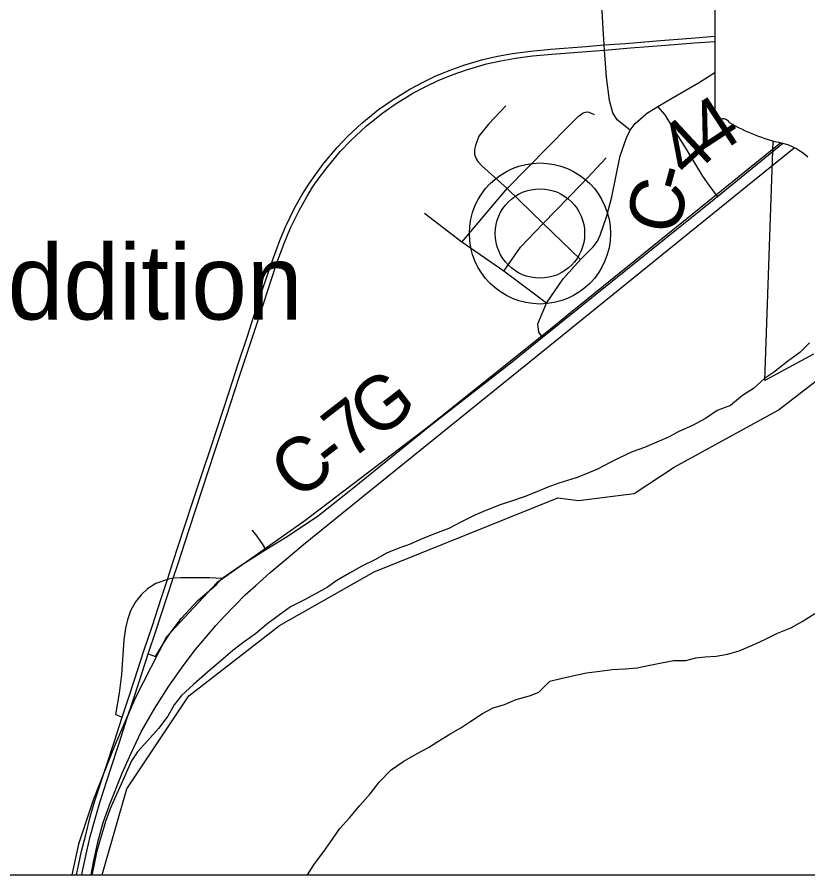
# Model space of a CAD drawing. Extents: x 0 to 34, y 0 to 22.
# Drawn here: x 6.612 to 7.446, y 14.1 to 15.005 of the extents above; entities that cross this region are included whole.
import ezdxf

# ---------------------------------------------------------------- set-up
doc = ezdxf.new("R2010")
doc.units = 0
for name, color, linetype in [('Default', 7, 'Continuous'), ('GM_X_County_Road', 7, 'Continuous'), ('GM_X_County_Road_Text', 7, 'Continuous'), ('GM_X_Interchange_Ramps', 7, 'Continuous'), ('GM_X_Major_River', 7, 'Continuous'), ('GM_X_Rail_Line', 7, 'Continuous'), ('GM_X_Section', 7, 'Continuous'), ('GM_X_State_Route', 7, 'Continuous'), ('GM_X_State_Shield', 7, 'Continuous'), ('GM_X_Township_Road', 7, 'Continuous'), ('GM_X_Unincorporated', 7, 'Continuous'), ('GM_X_Unincorporated_Location', 7, 'Continuous'), ('GM_X_Unincorporated_Text', 7, 'Continuous'), ('SH_Cut_Line', 7, 'Continuous'), ('SH_Data', 7, 'Continuous')]:
    doc.layers.add(name, color=color, linetype=linetype)

msp = doc.modelspace()

# ---------------------------------------------------------------- linework, layer by layer
at = {"layer": 'Default'}
for p, q in [((7.41471, 14.59015), (7.49082, 14.64909)), ((7.30502, 14.53008), (7.41471, 14.59015)), ((7.26298, 14.50243), (7.30502, 14.53008)), ((7.20414, 14.49508), (7.26298, 14.50243)), ((6.98847, 14.41957), (7.18239, 14.49774)), ((7.18239, 14.49774), (7.20414, 14.49508)), ((6.88889, 14.36327), (6.98847, 14.41957)), ((6.79317, 14.28882), (6.88889, 14.36327)), ((6.72773, 14.19078), (6.79317, 14.28882)), ((6.70166, 14.1), (6.72773, 14.19078)), ((2.1, 14.1), (6.70166, 14.1))]:
    msp.add_line(p, q, dxfattribs=at)
at = {"layer": 'GM_X_County_Road'}
for p, q in [((7.33067, 14.93583), (7.34804, 14.94647)), ((7.30175, 14.91894), (7.33067, 14.93583)), ((7.28799, 14.91083), (7.30175, 14.91894)), ((7.27602, 14.90331), (7.28799, 14.91083)), ((7.26391, 14.89277), (7.27522, 14.9028)), ((7.27522, 14.9028), (7.27602, 14.90331)), ((7.2588, 14.88565), (7.26391, 14.89277)), ((7.25497, 14.8778), (7.2588, 14.88565)), ((7.24804, 14.85864), (7.25497, 14.8778)), ((7.38738, 14.84583), (7.41968, 14.87194)), ((7.23926, 14.81549), (7.24804, 14.85864)), ((7.35075, 14.81566), (7.38738, 14.84583)), ((7.16638, 14.66727), (7.35075, 14.81566)), ((7.23399, 14.79526), (7.23926, 14.81549)), ((7.22693, 14.77491), (7.23399, 14.79526)), ((7.22416, 14.76879), (7.22693, 14.77491)), ((7.20645, 14.74914), (7.21973, 14.76272)), ((7.21973, 14.76272), (7.22416, 14.76879)), ((7.18784, 14.72871), (7.20645, 14.74914)), ((7.17033, 14.70324), (7.18784, 14.72871)), ((7.16121, 14.68126), (7.17033, 14.70324)), ((7.1623, 14.67251), (7.16121, 14.68126)), ((7.16638, 14.66727), (7.1623, 14.67251)), ((7.13461, 14.64157), (7.16638, 14.66727)), ((7.04873, 14.57481), (7.13461, 14.64157)), ((7.00271, 14.53742), (7.04873, 14.57481)), ((6.96588, 14.50753), (7.00271, 14.53742)), ((6.93001, 14.47931), (6.96588, 14.50753)), ((6.89679, 14.45693), (6.93001, 14.47931)), ((6.87441, 14.44317), (6.89679, 14.45693)), ((6.84717, 14.42621), (6.87441, 14.44317)), ((6.82785, 14.41273), (6.84717, 14.42621))]:
    msp.add_line(p, q, dxfattribs=at)
at = {"layer": 'GM_X_Interchange_Ramps'}
for p, q in [((6.77044, 14.41177), (6.75819, 14.40731)), ((6.77666, 14.41304), (6.77044, 14.41177)), ((6.78451, 14.41339), (6.77666, 14.41304)), ((6.81536, 14.41351), (6.78451, 14.41339)), ((6.82785, 14.41273), (6.81536, 14.41351)), ((6.82192, 14.40585), (6.82785, 14.41273)), ((6.7495, 14.40168), (6.74276, 14.39556)), ((6.75819, 14.40731), (6.7495, 14.40168)), ((6.80267, 14.38937), (6.82192, 14.40585)), ((6.74276, 14.39556), (6.73685, 14.38791)), ((6.73685, 14.38791), (6.73164, 14.37846)), ((6.78536, 14.37089), (6.80267, 14.38937)), ((6.73164, 14.37846), (6.72823, 14.36894)), ((6.72823, 14.36894), (6.72607, 14.36032)), ((6.77334, 14.35504), (6.78536, 14.37089)), ((6.72607, 14.36032), (6.72462, 14.34802)), ((6.76597, 14.34378), (6.77334, 14.35504)), ((6.72462, 14.34802), (6.72204, 14.31153)), ((6.75805, 14.33023), (6.76597, 14.34378)), ((6.75028, 14.33325), (6.75805, 14.33023)), ((6.72204, 14.31153), (6.71954, 14.29179)), ((6.71954, 14.29179), (6.71553, 14.26914)), ((6.71553, 14.26914), (6.7227, 14.26639))]:
    msp.add_line(p, q, dxfattribs=at)
at = {"layer": 'GM_X_Major_River'}
for p, q in [((7.44804, 14.66133), (7.43763, 14.65127)), ((7.43763, 14.65127), (7.42455, 14.64154)), ((7.42455, 14.64154), (7.41, 14.62989)), ((7.41, 14.62989), (7.40027, 14.62363)), ((7.40027, 14.62363), (7.38872, 14.61317)), ((7.38872, 14.61317), (7.37712, 14.60574)), ((7.37712, 14.60574), (7.36444, 14.59526)), ((7.35052, 14.59007), (7.33818, 14.58148)), ((7.36444, 14.59526), (7.35052, 14.59007)), ((7.33818, 14.58148), (7.3243, 14.57401)), ((7.3243, 14.57401), (7.31002, 14.56767)), ((7.2999, 14.56217), (7.28674, 14.55661)), ((7.31002, 14.56767), (7.2999, 14.56217)), ((7.28674, 14.55661), (7.27397, 14.55106)), ((7.2608, 14.54626), (7.24728, 14.53993)), ((7.27397, 14.55106), (7.2608, 14.54626)), ((7.23752, 14.53519), (7.22439, 14.52811)), ((7.24728, 14.53993), (7.23752, 14.53519)), ((7.22439, 14.52811), (7.21161, 14.52294)), ((7.20183, 14.51896), (7.18344, 14.51321)), ((7.21161, 14.52294), (7.20183, 14.51896)), ((7.17178, 14.50922), (7.16014, 14.50408)), ((7.18344, 14.51321), (7.17178, 14.50922)), ((7.14698, 14.49892), (7.13344, 14.49414)), ((7.16014, 14.50408), (7.14698, 14.49892)), ((7.12139, 14.49051), (7.10824, 14.48498)), ((7.13344, 14.49414), (7.12139, 14.49051)), ((7.10824, 14.48498), (7.09472, 14.47943)), ((7.08009, 14.47197), (7.06733, 14.4653)), ((7.09472, 14.47943), (7.08009, 14.47197)), ((7.06733, 14.4653), (7.05342, 14.46013)), ((7.03989, 14.45496), (7.02674, 14.44905)), ((7.05342, 14.46013), (7.03989, 14.45496)), ((7.01471, 14.44466), (7.00155, 14.43951)), ((7.02674, 14.44905), (7.01471, 14.44466)), ((7.00155, 14.43951), (6.98994, 14.43286)), ((6.97568, 14.42578), (6.96256, 14.41835)), ((6.98994, 14.43286), (6.97568, 14.42578)), ((6.96256, 14.41835), (6.94907, 14.41053)), ((6.94907, 14.41053), (6.93936, 14.40353)), ((6.93936, 14.40353), (6.92661, 14.39649)), ((6.91424, 14.38982), (6.90036, 14.38275)), ((6.92661, 14.39649), (6.91424, 14.38982)), ((6.90036, 14.38275), (6.88727, 14.37343)), ((6.88727, 14.37343), (6.87494, 14.36411)), ((7.44009, 14.36721), (7.45356, 14.37581)), ((6.87494, 14.36411), (6.86338, 14.35443)), ((7.42809, 14.36053), (7.44009, 14.36721)), ((6.86338, 14.35443), (6.85142, 14.34588)), ((7.40142, 14.34864), (7.41418, 14.35496)), ((7.41418, 14.35496), (7.42809, 14.36053)), ((6.85142, 14.34588), (6.83947, 14.33657)), ((7.3879, 14.34232), (7.40142, 14.34864)), ((6.83947, 14.33657), (6.82642, 14.32534)), ((7.36156, 14.33271), (7.37361, 14.33636)), ((7.37361, 14.33636), (7.3879, 14.34232)), ((7.29163, 14.3238), (7.30484, 14.32633)), ((7.30484, 14.32633), (7.31735, 14.32619)), ((7.31735, 14.32619), (7.3279, 14.32904)), ((7.3279, 14.32904), (7.33774, 14.32999)), ((7.33774, 14.32999), (7.34947, 14.33059)), ((7.34947, 14.33059), (7.36156, 14.33271)), ((6.82642, 14.32534), (6.81262, 14.31372)), ((7.23985, 14.31675), (7.25348, 14.31739)), ((7.25348, 14.31739), (7.26596, 14.31838)), ((7.26596, 14.31838), (7.27766, 14.32088)), ((7.27766, 14.32088), (7.29163, 14.3238)), ((6.81262, 14.31372), (6.79808, 14.30096)), ((7.18687, 14.30746), (7.21263, 14.3132)), ((7.21263, 14.3132), (7.22662, 14.31498)), ((7.22662, 14.31498), (7.23985, 14.31675)), ((6.79808, 14.30096), (6.78541, 14.28936)), ((7.16229, 14.2929), (7.17382, 14.30448)), ((7.17382, 14.30448), (7.18687, 14.30746)), ((7.15252, 14.28894), (7.16229, 14.2929)), ((6.78541, 14.28936), (6.77764, 14.27936)), ((7.12619, 14.27975), (7.13859, 14.2849)), ((7.13859, 14.2849), (7.15252, 14.28894)), ((6.77764, 14.27936), (6.77104, 14.26749)), ((7.10289, 14.27025), (7.11414, 14.27613)), ((7.11414, 14.27613), (7.12619, 14.27975)), ((6.77104, 14.26749), (6.76105, 14.25443)), ((7.09055, 14.26207), (7.10289, 14.27025)), ((6.76105, 14.25443), (6.74954, 14.24133)), ((7.06957, 14.24919), (7.08007, 14.25506)), ((7.08007, 14.25506), (7.09055, 14.26207)), ((7.05572, 14.24061), (7.06957, 14.24919)), ((6.74954, 14.24133), (6.73877, 14.22977)), ((7.04599, 14.23437), (7.05572, 14.24061)), ((6.73877, 14.22977), (6.7325, 14.22018)), ((7.01975, 14.21988), (7.03399, 14.22809)), ((7.03399, 14.22809), (7.04599, 14.23437)), ((6.7325, 14.22018), (6.72157, 14.19572)), ((7.00666, 14.21093), (7.01975, 14.21988)), ((6.99402, 14.19782), (7.00666, 14.21093)), ((6.72157, 14.19572), (6.71502, 14.18082)), ((6.98439, 14.18551), (6.99402, 14.19782)), ((6.97363, 14.17319), (6.98439, 14.18551)), ((6.71502, 14.18082), (6.70991, 14.16973)), ((6.96251, 14.1601), (6.97363, 14.17319)), ((6.70991, 14.16973), (6.70522, 14.15637)), ((6.70522, 14.15637), (6.70237, 14.14646)), ((6.95248, 14.14893), (6.96251, 14.1601)), ((6.70237, 14.14646), (6.69842, 14.13388)), ((6.94547, 14.13857), (6.95248, 14.14893)), ((6.93549, 14.12475), (6.94547, 14.13857)), ((6.69842, 14.13388), (6.69557, 14.12359)), ((6.69557, 14.12359), (6.69279, 14.10951)), ((6.9255, 14.11168), (6.93549, 14.12475)), ((6.69279, 14.10951), (6.69073, 14.1)), ((6.91834, 14.1), (6.9255, 14.11168))]:
    msp.add_line(p, q, dxfattribs=at)
at = {"layer": 'GM_X_Rail_Line'}
for p, q in [((7.41781, 14.87237), (7.19564, 14.69284)), ((7.38977, 14.83342), (7.43184, 14.86724)), ((7.17225, 14.65714), (7.38977, 14.83342)), ((7.19564, 14.69284), (7.17998, 14.68012)), ((7.17998, 14.68012), (7.04751, 14.57406)), ((6.95475, 14.48147), (7.17225, 14.65714)), ((7.04751, 14.57406), (6.91535, 14.47339)), ((6.91408, 14.44862), (6.95475, 14.48147)), ((6.91535, 14.47339), (6.82266, 14.40828)), ((6.89558, 14.43318), (6.91408, 14.44862)), ((6.87876, 14.41893), (6.89558, 14.43318)), ((6.86372, 14.40538), (6.87876, 14.41893)), ((6.82266, 14.40828), (6.76935, 14.35099)), ((6.85254, 14.39538), (6.86372, 14.40538)), ((6.84205, 14.3847), (6.85254, 14.39538)), ((6.83028, 14.37253), (6.84205, 14.3847)), ((6.82137, 14.36303), (6.83028, 14.37253)), ((6.81197, 14.35185), (6.82137, 14.36303)), ((6.76935, 14.35099), (6.73676, 14.28711)), ((6.8, 14.3377), (6.81197, 14.35185)), ((6.78694, 14.32048), (6.8, 14.3377)), ((6.7718, 14.29901), (6.78694, 14.32048)), ((6.75716, 14.27576), (6.7718, 14.29901)), ((6.73676, 14.28711), (6.71426, 14.23521)), ((6.74291, 14.25073), (6.75716, 14.27576)), ((6.73222, 14.22837), (6.74291, 14.25073)), ((6.71426, 14.23521), (6.69231, 14.17996)), ((6.72282, 14.20719), (6.73222, 14.22837)), ((6.70907, 14.17296), (6.72282, 14.20719)), ((6.69231, 14.17996), (6.6765, 14.13243)), ((6.70264, 14.15515), (6.70907, 14.17296)), ((6.69749, 14.13605), (6.70264, 14.15515)), ((6.69284, 14.11527), (6.69749, 14.13605)), ((6.6765, 14.13243), (6.6697, 14.1)), ((6.69008, 14.1), (6.69284, 14.11527))]:
    msp.add_line(p, q, dxfattribs=at)
at = {"layer": 'GM_X_Section'}
for p, q in [((7.40091, 14.62176), (7.40946, 14.87449)), ((7.45214, 14.64934), (7.40091, 14.62176))]:
    msp.add_line(p, q, dxfattribs=at)
at = {"layer": 'GM_X_State_Route'}
for p, q in [((7.25332, 14.97736), (7.2908, 14.98033)), ((7.2908, 14.98033), (7.32306, 14.98284)), ((7.29623, 14.97535), (7.32653, 14.97779)), ((7.32306, 14.98284), (7.34804, 14.98491)), ((7.32653, 14.97779), (7.34804, 14.97948)), ((7.13466, 14.9665), (7.15371, 14.96921)), ((7.15371, 14.96921), (7.17491, 14.97125)), ((7.17491, 14.97125), (7.21182, 14.97417)), ((7.17592, 14.96597), (7.21254, 14.96889)), ((7.21182, 14.97417), (7.23118, 14.97563)), ((7.21254, 14.96889), (7.23148, 14.9702)), ((7.23118, 14.97563), (7.25332, 14.97736)), ((7.23148, 14.9702), (7.25897, 14.9725)), ((7.25897, 14.9725), (7.29623, 14.97535)), ((7.08303, 14.95433), (7.10334, 14.96029)), ((7.10334, 14.96029), (7.11874, 14.96373)), ((7.11874, 14.96373), (7.13466, 14.9665)), ((7.12212, 14.95888), (7.13776, 14.96159)), ((7.13776, 14.96159), (7.15562, 14.96403)), ((7.15562, 14.96403), (7.17592, 14.96597)), ((7.06769, 14.94864), (7.08303, 14.95433)), ((7.08612, 14.94957), (7.10711, 14.95569)), ((7.10711, 14.95569), (7.12212, 14.95888)), ((7.04031, 14.93648), (7.05296, 14.9426)), ((7.05296, 14.9426), (7.06769, 14.94864)), ((7.0563, 14.93824), (7.07104, 14.94429)), ((7.07104, 14.94429), (7.08612, 14.94957)), ((7.0262, 14.92904), (7.04031, 14.93648)), ((7.04365, 14.93212), (7.0563, 14.93824)), ((7.00743, 14.91751), (7.0262, 14.92904)), ((7.01078, 14.91315), (7.02954, 14.92469)), ((7.02954, 14.92469), (7.04365, 14.93212)), ((6.99334, 14.90745), (7.00743, 14.91751)), ((6.97575, 14.89315), (6.99334, 14.90745)), ((6.99763, 14.90417), (7.01078, 14.91315)), ((6.98054, 14.89021), (6.99763, 14.90417)), ((6.96038, 14.87893), (6.97575, 14.89315)), ((6.96372, 14.87458), (6.98054, 14.89021)), ((6.9494, 14.86753), (6.96038, 14.87893)), ((6.95274, 14.86318), (6.96372, 14.87458)), ((6.9355, 14.85085), (6.9494, 14.86753)), ((6.93884, 14.8465), (6.95274, 14.86318)), ((6.92625, 14.83834), (6.9355, 14.85085)), ((6.9296, 14.83399), (6.93884, 14.8465)), ((6.92028, 14.82979), (6.92625, 14.83834)), ((6.92362, 14.82544), (6.9296, 14.83399)), ((6.91274, 14.81782), (6.92028, 14.82979)), ((6.91743, 14.81529), (6.92362, 14.82544)), ((6.90501, 14.80419), (6.91274, 14.81782)), ((6.9093, 14.80083), (6.91743, 14.81529)), ((6.89499, 14.78363), (6.90501, 14.80419)), ((6.90032, 14.78257), (6.9093, 14.80083)), ((6.88914, 14.76948), (6.89499, 14.78363)), ((6.89325, 14.76559), (6.90032, 14.78257)), ((6.88126, 14.74818), (6.88914, 14.76948)), ((6.88567, 14.74481), (6.89325, 14.76559)), ((6.87124, 14.71879), (6.88126, 14.74818)), ((6.8717, 14.70262), (6.88567, 14.74481)), ((6.86408, 14.69707), (6.87124, 14.71879)), ((6.86009, 14.66739), (6.8717, 14.70262)), ((6.85484, 14.66841), (6.86408, 14.69707)), ((6.84524, 14.63923), (6.85484, 14.66841)), ((6.84619, 14.62527), (6.86009, 14.66739)), ((6.83589, 14.61083), (6.84524, 14.63923)), ((6.83229, 14.58308), (6.84619, 14.62527)), ((6.82848, 14.58833), (6.83589, 14.61083)), ((6.81694, 14.55273), (6.82848, 14.58833)), ((6.82089, 14.54805), (6.83229, 14.58308)), ((6.80723, 14.52354), (6.81694, 14.55273)), ((6.80713, 14.50621), (6.82089, 14.54805)), ((6.79778, 14.49494), (6.80723, 14.52354)), ((6.79344, 14.46437), (6.80713, 14.50621)), ((6.78828, 14.46607), (6.79778, 14.49494)), ((6.77669, 14.43052), (6.78828, 14.46607)), ((6.78176, 14.42864), (6.79344, 14.46437)), ((6.77044, 14.41177), (6.77669, 14.43052)), ((6.77666, 14.41304), (6.78176, 14.42864)), ((6.76385, 14.39173), (6.77044, 14.41177)), ((6.76979, 14.3925), (6.77666, 14.41304)), ((6.75461, 14.36322), (6.76385, 14.39173)), ((6.75819, 14.35719), (6.76979, 14.3925)), ((6.74532, 14.3353), (6.75461, 14.36322)), ((6.75028, 14.33325), (6.75819, 14.35719)), ((6.73611, 14.30688), (6.74532, 14.3353)), ((6.74107, 14.30484), (6.75028, 14.33325)), ((6.72909, 14.28547), (6.73611, 14.30688)), ((6.73405, 14.28343), (6.74107, 14.30484)), ((6.7227, 14.26639), (6.72909, 14.28547)), ((6.72757, 14.26452), (6.73405, 14.28343)), ((6.71449, 14.24092), (6.7227, 14.26639)), ((6.71981, 14.24003), (6.72757, 14.26452)), ((6.70504, 14.21215), (6.71449, 14.24092)), ((6.71064, 14.21213), (6.71981, 14.24003)), ((6.69334, 14.17608), (6.70504, 14.21215)), ((6.69903, 14.17627), (6.71064, 14.21213)), ((6.68911, 14.16115), (6.69334, 14.17608)), ((6.69408, 14.15909), (6.69903, 14.17627)), ((6.68422, 14.14234), (6.68911, 14.16115)), ((6.68909, 14.14047), (6.69408, 14.15909)), ((6.67993, 14.12502), (6.68422, 14.14234)), ((6.68548, 14.12491), (6.68909, 14.14047)), ((6.67544, 14.10503), (6.67993, 14.12502)), ((6.68089, 14.10378), (6.68548, 14.12491)), ((6.67452, 14.1), (6.67544, 14.10503)), ((6.68014, 14.1), (6.68089, 14.10378))]:
    msp.add_line(p, q, dxfattribs=at)
at = {"layer": 'GM_X_State_Shield'}
msp.add_line((7.34804, 15.10094), (7.34804, 14.90081), dxfattribs=at)
for centre, radius, start, end in [((7.35109, 14.90038), 0.00308, 171.95839, 258.30661), ((7.35156, 14.92085), 0.02352, 267.33899, 280.60386), ((7.35637, 14.88927), 0.00848, 29.74838, 93.27175), ((7.46343, 15.06907), 0.20192, 240.41292, 257.1985), ((7.40323, 14.81091), 0.06318, 47.18416, 75.83597)]:
    msp.add_arc(centre, radius, start, end, dxfattribs=at)
at = {"layer": 'GM_X_Township_Road'}
for p, q in [((7.22991, 14.99857), (7.22693, 15.06105)), ((7.23118, 14.97563), (7.22991, 14.99857)), ((7.23148, 14.9702), (7.23118, 14.97563)), ((7.23374, 14.94158), (7.23148, 14.9702)), ((7.23673, 14.91696), (7.23374, 14.94158)), ((7.24038, 14.90419), (7.23673, 14.91696)), ((7.1275, 14.91151), (7.10922, 14.89218)), ((7.29557, 14.90178), (7.28799, 14.91083)), ((7.19379, 14.88996), (7.20397, 14.90025)), ((7.20397, 14.90025), (7.20895, 14.90392)), ((7.20895, 14.90392), (7.21146, 14.90482)), ((7.21146, 14.90482), (7.21419, 14.90497)), ((7.21419, 14.90497), (7.21701, 14.90415)), ((7.21701, 14.90415), (7.22074, 14.90235)), ((7.24512, 14.89652), (7.24038, 14.90419)), ((7.2588, 14.88565), (7.24512, 14.89652)), ((7.30384, 14.8885), (7.29557, 14.90178)), ((7.10922, 14.89218), (7.09904, 14.87939)), ((7.1288, 14.82429), (7.19379, 14.88996)), ((7.31802, 14.86564), (7.30384, 14.8885)), ((7.09904, 14.87939), (7.09539, 14.86973)), ((7.09539, 14.86973), (7.09439, 14.86541)), ((7.09439, 14.86541), (7.09456, 14.86155)), ((7.09456, 14.86155), (7.09461, 14.86059)), ((7.09461, 14.86059), (7.09593, 14.85618)), ((7.32608, 14.85243), (7.31802, 14.86564)), ((7.09593, 14.85618), (7.09814, 14.85272)), ((7.09814, 14.85272), (7.10208, 14.8481)), ((7.21358, 14.83533), (7.23325, 14.85639)), ((7.33525, 14.83721), (7.32608, 14.85243)), ((7.10208, 14.8481), (7.1288, 14.82429)), ((7.20702, 14.82856), (7.21358, 14.83533)), ((7.34206, 14.82769), (7.33525, 14.83721)), ((7.08124, 14.76749), (7.1288, 14.82429)), ((7.1288, 14.82429), (7.16702, 14.7873)), ((7.16702, 14.7873), (7.20702, 14.82856)), ((7.35075, 14.81566), (7.34206, 14.82769)), ((7.08124, 14.76749), (7.04162, 14.79769)), ((7.14293, 14.76244), (7.16702, 14.7873)), ((7.16702, 14.7873), (7.20645, 14.74914)), ((7.12556, 14.737), (7.08124, 14.76749)), ((7.12556, 14.737), (7.14293, 14.76244)), ((7.17033, 14.70324), (7.12556, 14.737)), ((6.86399, 14.45874), (6.85988, 14.46352)), ((6.87066, 14.44942), (6.86399, 14.45874)), ((6.87441, 14.44317), (6.87066, 14.44942))]:
    msp.add_line(p, q, dxfattribs=at)
at = {"layer": 'GM_X_Unincorporated'}
for radius in [0.0744, 0.04716]:
    msp.add_circle((7.16352, 14.77671), radius, dxfattribs=at)
at = {"layer": 'GM_X_Unincorporated_Location'}
msp.add_line((7.16352, 14.77671), (7.16352, 14.77671), dxfattribs=at)
at = {"layer": 'SH_Cut_Line'}
for p, q in [((7.41471, 14.59015), (7.49082, 14.64909)), ((7.30502, 14.53008), (7.41471, 14.59015)), ((7.26298, 14.50243), (7.30502, 14.53008)), ((7.20414, 14.49508), (7.26298, 14.50243)), ((6.98847, 14.41957), (7.18239, 14.49774)), ((7.18239, 14.49774), (7.20414, 14.49508)), ((6.88889, 14.36327), (6.98847, 14.41957)), ((6.79317, 14.28882), (6.88889, 14.36327)), ((6.72773, 14.19078), (6.79317, 14.28882)), ((6.70166, 14.1), (6.72773, 14.19078)), ((2.1, 14.1), (6.70166, 14.1))]:
    msp.add_line(p, q, dxfattribs=at)
at = {"layer": 'SH_Data'}
msp.add_line((2.1, 14.1), (8.9, 14.1), dxfattribs=at)

# ---------------------------------------------------------------- texts
at = {"layer": 'GM_X_County_Road_Text'}
for s, rotation, p in [('4', 33.3056, (7.34403, 14.85511)), ('4', 42.82565, (7.32053, 14.83304)), ('-', 74.74371, (7.31872, 14.8178)), ('C', 77.00876, (7.30845, 14.77324)), ('G', 37.79702, (6.99046, 14.55761)), ('7', 37.79395, (6.96302, 14.53633)), ('C', 36.86754, (6.90689, 14.49377)), ('-', 37.77707, (6.94473, 14.52216))]:
    msp.add_text(s, height=0.05682, rotation=rotation, dxfattribs=at).set_placement(p)
at = {"layer": 'GM_X_Unincorporated_Text'}
msp.add_text('Pottery Addition', height=0.0789773, rotation=0.00001, dxfattribs=at).set_placement((6.16755, 14.68597))

doc.saveas('drawing.dxf')
